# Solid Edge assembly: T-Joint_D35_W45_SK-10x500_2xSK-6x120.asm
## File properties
Author: fknapp
Template: iso metric assembly.asm
Last saved by: fknapp
Revision: 14
Application: Solid Edge
Username: fknapp
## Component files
T-Joint_D35_W45.par
SK Schraube 6x120_ohne_Gewinde.par
SK Schraube 10x500_ohne_Gewinde_22042020.par
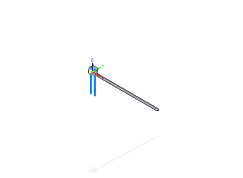
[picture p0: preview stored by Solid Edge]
